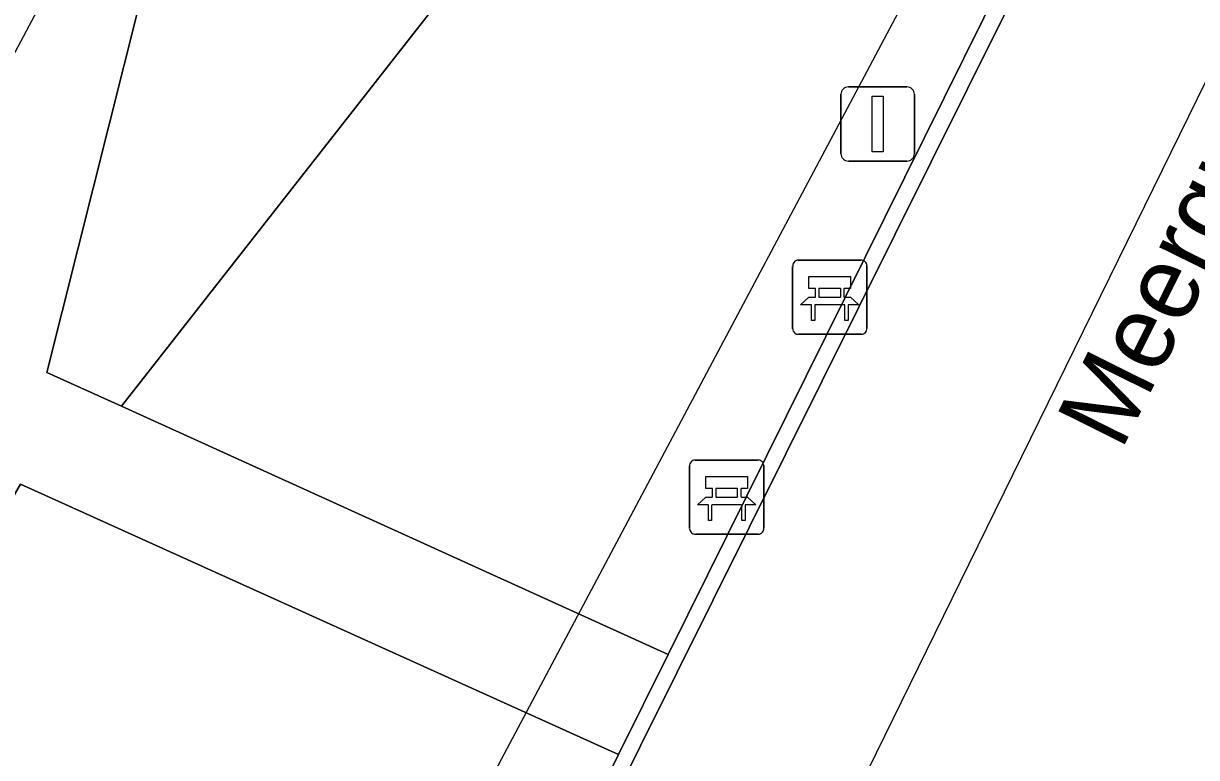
# Model space of a CAD drawing. Extents: x 155640 to 156811, y 382821 to 384049.
# Drawn here: x 156506.26 to 156522.06, y 383594.53 to 383604.42 of the extents above; entities that cross this region are included whole.
import ezdxf

# ---------------------------------------------------------------- set-up
doc = ezdxf.new("R2010")
doc.units = 0
for name, color, linetype in [('IMGEO_Bank', 7, 'Continuous'), ('IMGEO_Groenvoorziening', 7, 'Continuous'), ('IMGEO_Lichtmast', 7, 'Continuous'), ('IMGEO_Lijnafwatering', 7, 'Continuous'), ('IMGEO_Muur', 7, 'Continuous'), ('IMGEO_Openbare_ruimte_label', 7, 'Continuous'), ('IMGEO_Pand_vergunning_verleend', 7, 'Continuous'), ('IMGEO_Voetgangersgebied_open', 7, 'Continuous'), ('IMGEO_Voetpad_halfverhard', 7, 'Continuous')]:
    doc.layers.add(name, color=color, linetype=linetype)

msp = doc.modelspace()

# ---------------------------------------------------------------- linework, layer by layer
at = {"layer": 'IMGEO_Bank'}
for p, q in [((156516.618, 383600.309), (156516.618, 383601.15)), ((156516.618, 383601.15), (156516.618, 383600.309)), ((156516.693, 383601.234), (156517.534, 383601.234)), ((156517.534, 383601.234), (156516.693, 383601.234)), ((156517.618, 383601.159), (156517.618, 383600.318)), ((156517.618, 383600.318), (156517.618, 383601.159)), ((156516.927, 383600.74), (156516.927, 383600.846)), ((156516.971, 383600.846), (156516.971, 383600.74)), ((156517.259, 383600.852), (156516.977, 383600.852)), ((156517.265, 383600.74), (156517.265, 383600.846)), ((156517.309, 383600.846), (156517.309, 383600.74)), ((156516.977, 383600.734), (156517.259, 383600.734)), ((156517.315, 383600.632), (156516.922, 383600.632)), ((156517.543, 383600.234), (156516.702, 383600.234)), ((156516.702, 383600.234), (156517.543, 383600.234)), ((156515.23, 383597.615), (156515.23, 383598.456)), ((156515.23, 383598.456), (156515.23, 383597.615)), ((156515.305, 383598.54), (156516.146, 383598.54)), ((156516.146, 383598.54), (156515.305, 383598.54)), ((156516.23, 383598.465), (156516.23, 383597.624)), ((156516.23, 383597.624), (156516.23, 383598.465)), ((156515.539, 383598.046), (156515.539, 383598.152)), ((156515.583, 383598.152), (156515.583, 383598.046)), ((156515.871, 383598.158), (156515.589, 383598.158)), ((156515.877, 383598.046), (156515.877, 383598.152)), ((156515.921, 383598.152), (156515.921, 383598.046)), ((156515.589, 383598.04), (156515.871, 383598.04)), ((156515.927, 383597.938), (156515.534, 383597.938)), ((156516.155, 383597.54), (156515.314, 383597.54)), ((156515.314, 383597.54), (156516.155, 383597.54))]:
    msp.add_line(p, q, dxfattribs=at)
for points in [[(156516.921, 383600.852), (156516.835, 383600.852), (156516.835, 383601.013), (156517.398, 383601.013), (156517.398, 383600.852), (156517.315, 383600.852)], [(156516.865, 383600.632), (156516.723, 383600.632), (156516.835, 383600.734), (156516.921, 383600.734)], [(156517.315, 383600.734), (156517.398, 383600.734), (156517.51, 383600.632), (156517.371, 383600.632)], [(156516.915, 383600.625), (156516.915, 383600.418), (156516.872, 383600.418), (156516.872, 383600.625)], [(156517.365, 383600.625), (156517.365, 383600.418), (156517.321, 383600.418), (156517.321, 383600.625)], [(156515.533, 383598.158), (156515.447, 383598.158), (156515.447, 383598.319), (156516.01, 383598.319), (156516.01, 383598.158), (156515.927, 383598.158)], [(156515.477, 383597.938), (156515.335, 383597.938), (156515.447, 383598.04), (156515.533, 383598.04)], [(156515.927, 383598.04), (156516.01, 383598.04), (156516.122, 383597.938), (156515.983, 383597.938)], [(156515.527, 383597.931), (156515.527, 383597.724), (156515.484, 383597.724), (156515.484, 383597.931)], [(156515.977, 383597.931), (156515.977, 383597.724), (156515.933, 383597.724), (156515.933, 383597.931)]]:
    msp.add_lwpolyline(points, dxfattribs=at)
for centre, radius, start, end in [((156516.696, 383601.156), 0.0779, 92.4484, 184.2845), ((156516.696, 383601.156), 0.0779, 92.4484, 184.2845), ((156517.54, 383601.156), 0.0779, 2.4484, 94.2845), ((156517.54, 383601.156), 0.0779, 2.4484, 94.2845), ((156516.92, 383600.845), 0.00671, 2.8957, 87.1043), ((156516.977, 383600.845), 0.00671, 92.8957, 177.1043), ((156517.259, 383600.845), 0.00671, 2.8957, 87.1043), ((156517.316, 383600.845), 0.00671, 92.8957, 177.1043), ((156516.92, 383600.741), 0.00671, 272.8957, 357.1043), ((156516.977, 383600.741), 0.00671, 182.8957, 267.1043), ((156517.259, 383600.741), 0.00671, 272.8957, 357.1043), ((156517.316, 383600.741), 0.00671, 182.8957, 267.1043), ((156516.865, 383600.625), 0.00671, 2.8957, 87.1043), ((156516.922, 383600.625), 0.00671, 92.8957, 177.1043), ((156517.314, 383600.625), 0.00671, 2.8957, 87.1043), ((156517.371, 383600.625), 0.00671, 92.8957, 177.1043), ((156516.696, 383600.312), 0.0779, 182.4484, 274.2845), ((156516.696, 383600.312), 0.0779, 182.4484, 274.2845), ((156517.54, 383600.312), 0.0779, 272.4484, 4.2845), ((156517.54, 383600.312), 0.0779, 272.4484, 4.2845), ((156515.308, 383598.462), 0.0779, 92.4484, 184.2845), ((156515.308, 383598.462), 0.0779, 92.4484, 184.2845), ((156516.152, 383598.462), 0.0779, 2.4484, 94.2845), ((156516.152, 383598.462), 0.0779, 2.4484, 94.2845), ((156515.532, 383598.151), 0.00671, 2.8957, 87.1043), ((156515.589, 383598.151), 0.00671, 92.8957, 177.1043), ((156515.871, 383598.151), 0.00671, 2.8957, 87.1043), ((156515.928, 383598.151), 0.00671, 92.8957, 177.1043), ((156515.532, 383598.047), 0.00671, 272.8957, 357.1043), ((156515.589, 383598.047), 0.00671, 182.8957, 267.1043), ((156515.871, 383598.047), 0.00671, 272.8957, 357.1043), ((156515.928, 383598.047), 0.00671, 182.8957, 267.1043), ((156515.477, 383597.931), 0.00671, 2.8957, 87.1043), ((156515.534, 383597.931), 0.00671, 92.8957, 177.1043), ((156515.926, 383597.931), 0.00671, 2.8957, 87.1043), ((156515.983, 383597.931), 0.00671, 92.8957, 177.1043), ((156515.308, 383597.618), 0.0779, 182.4484, 274.2845), ((156515.308, 383597.618), 0.0779, 182.4484, 274.2845), ((156516.152, 383597.618), 0.0779, 272.4484, 4.2845), ((156516.152, 383597.618), 0.0779, 272.4484, 4.2845)]:
    msp.add_arc(centre, radius, start, end, dxfattribs=at)
at = {"layer": 'IMGEO_Groenvoorziening'}
for points in [[(156526.36, 383618.972), (156514.787, 383615.84), (156515.844, 383609.825), (156507.579, 383599.264), (156514.94, 383595.917)], [(156514.787, 383615.84), (156510.318, 383614.631), (156506.574, 383599.721), (156507.579, 383599.264), (156515.844, 383609.825)], [(156514.272, 383594.571), (156506.22, 383598.214), (156503.929, 383594.258), (156507.686, 383592.265), (156509.712, 383588.822), (156511.111, 383588.199)]]:
    msp.add_lwpolyline(points, close=True, dxfattribs=at)
at = {"layer": 'IMGEO_Lichtmast'}
for p, q in [((156517.368, 383603.569), (156518.158, 383603.569)), ((156518.158, 383603.569), (156517.368, 383603.569)), ((156517.268, 383602.669), (156517.268, 383603.469)), ((156517.268, 383603.469), (156517.268, 383602.669)), ((156518.258, 383603.469), (156518.258, 383602.669)), ((156518.258, 383602.669), (156518.258, 383603.469)), ((156518.158, 383602.569), (156517.368, 383602.569)), ((156517.368, 383602.569), (156518.158, 383602.569))]:
    msp.add_line(p, q, dxfattribs=at)
msp.add_lwpolyline([(156517.688, 383603.444), (156517.838, 383603.444), (156517.838, 383602.694), (156517.688, 383602.694), (156517.688, 383603.444)], dxfattribs=at)
for centre, start, end in [((156517.368, 383603.469), 90, 180), ((156517.368, 383603.469), 90, 180), ((156518.158, 383603.469), 0, 90), ((156518.158, 383603.469), 360, 90), ((156517.368, 383602.669), 180, 270), ((156517.368, 383602.669), 180, 270), ((156518.158, 383602.669), 270, 0), ((156518.158, 383602.669), 270, 0)]:
    msp.add_arc(centre, 0.1, start, end, dxfattribs=at)
at = {"layer": 'IMGEO_Lijnafwatering'}
for points in [[(156518.88, 383596.903), (156527.152, 383613.781)], [(156510.608, 383580.026), (156518.88, 383596.903)]]:
    msp.add_lwpolyline(points, dxfattribs=at)
at = {"layer": 'IMGEO_Muur'}
msp.add_lwpolyline([(156476.681, 383604.033), (156474.856, 383605.458), (156469.299, 383609.796), (156464.709, 383619.641), (156464.271, 383620.58), (156461.62, 383626.266), (156460.994, 383627.61), (156454.752, 383640.999), (156454.553, 383640.906), (156469.136, 383609.655), (156507.234, 383579.938), (156533.646, 383633.045), (156533.479, 383633.068), (156533.395, 383632.884), (156533.247, 383632.905), (156531.663, 383629.7), (156527.439, 383621.156), (156526.36, 383618.972), (156514.94, 383595.917), (156514.272, 383594.571), (156511.111, 383588.199), (156507.172, 383580.262), (156499.454, 383586.279), (156498.234, 383587.23)], close=True, dxfattribs=at)
at = {"layer": 'IMGEO_Pand_vergunning_verleend'}
for points in [[(156467.395, 383611.689), (156495.139, 383590.315), (156494.276, 383588.537), (156496.866, 383586.607), (156522.239, 383634.29)], [(156533.045, 383632.833), (156494.418, 383560.103), (156449.18, 383594.892), (156450.711, 383595.595), (156449.358, 383598.538), (156447.864, 383597.851), (156446.042, 383601.815), (156447.521, 383602.495), (156446.189, 383605.394)]]:
    msp.add_lwpolyline(points, dxfattribs=at)
at = {"layer": 'IMGEO_Voetgangersgebied_open'}
msp.add_lwpolyline([(156469.136, 383609.655), (156454.553, 383640.906), (156430.689, 383629.765), (156423.924, 383644.238), (156458.601, 383660.428), (156460.51, 383661.282), (156520.187, 383653.02), (156525.098, 383652.346), (156525.335, 383654.043), (156542.861, 383651.582), (156541.504, 383648.852), (156533.646, 383633.045), (156507.234, 383579.938)], close=True, dxfattribs=at)
at = {"layer": 'IMGEO_Voetpad_halfverhard'}
msp.add_lwpolyline([(156474.856, 383605.458), (156476.681, 383604.033), (156484.318, 383604.225), (156488.004, 383604.317), (156502.253, 383599.411), (156503.052, 383596.802), (156503.254, 383596.041), (156498.234, 383587.23), (156499.454, 383586.279), (156503.929, 383594.258), (156506.22, 383598.214), (156514.272, 383594.571), (156514.94, 383595.917), (156507.579, 383599.264), (156506.574, 383599.721), (156510.318, 383614.631)], dxfattribs=at)

# ---------------------------------------------------------------- texts
at = {"layer": 'IMGEO_Openbare_ruimte_label'}
msp.add_text('Meergras', height=1, rotation=63.5374, dxfattribs=at).set_placement((156521.043, 383598.655))

doc.saveas('drawing.dxf')
